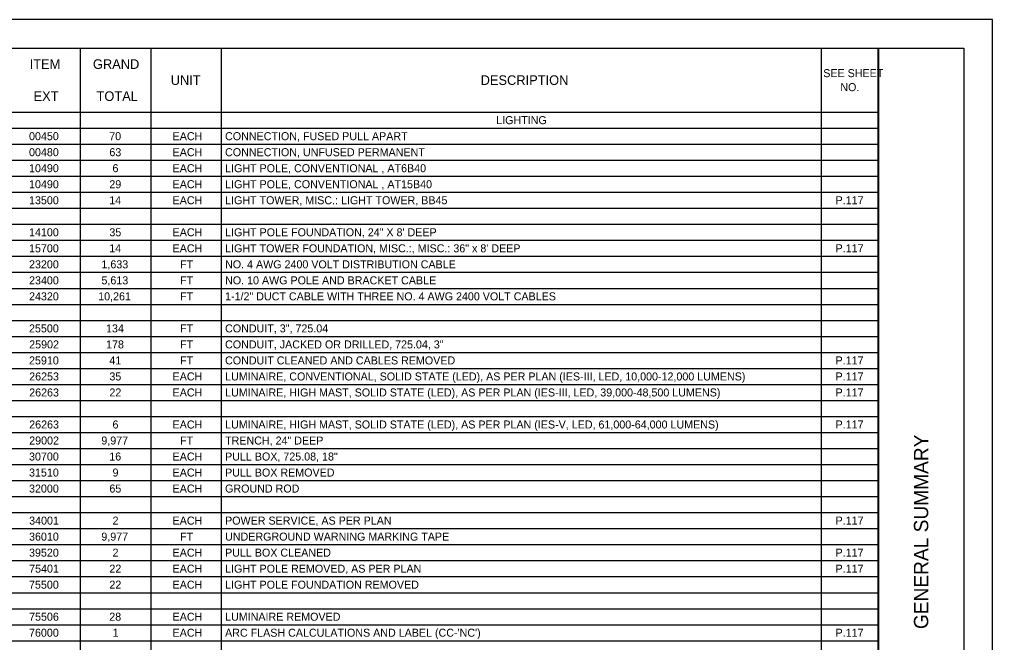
# Model space of a CAD drawing. Extents: x 0 to 34, y 0 to 22.
# Drawn here: x 16.98 to 34, y 11.11 to 22 of the extents above; entities that cross this region are included whole.
import ezdxf

# ---------------------------------------------------------------- set-up
doc = ezdxf.new("R2010")
doc.units = 0
for name, color, linetype in [('SH_Border', 7, 'Continuous'), ('SH_Cut_Line', 7, 'Continuous'), ('SH_Data', 7, 'Continuous'), ('SH_Text', 7, 'Continuous')]:
    doc.layers.add(name, color=color, linetype=linetype)

msp = doc.modelspace()

# ---------------------------------------------------------------- linework, layer by layer
at = {"layer": 'SH_Border'}
msp.add_line((32, 0.5), (32, 21.5), dxfattribs=at)
msp.add_lwpolyline([(1.5, 21.5), (33.5, 21.5), (33.5, 0.5), (1.5, 0.5)], close=True, dxfattribs=at)
at = {"layer": 'SH_Cut_Line'}
msp.add_lwpolyline([(0, 0), (34, 0), (34, 22), (0, 22)], close=True, dxfattribs=at)
at = {"layer": 'SH_Text'}
for p, q in [((1.5, 21.5), (32.004, 21.5)), ((18.036, 21.5), (18.036, 0.5)), ((19.272, 21.5), (19.272, 0.5)), ((20.507, 21.5), (20.507, 0.5)), ((30.999, 21.5), (30.999, 0.5)), ((32.004, 21.5), (32.004, 0.5)), ((1.5, 20.38), (32.004, 20.38)), ((1.5, 20.1), (32.004, 20.1)), ((1.5, 19.82), (32.004, 19.82)), ((1.5, 19.54), (32.004, 19.54)), ((1.5, 19.26), (32.004, 19.26)), ((1.5, 18.98), (32.004, 18.98)), ((1.5, 18.7), (32.004, 18.7)), ((1.5, 18.42), (32.004, 18.42)), ((1.5, 18.14), (32.004, 18.14)), ((1.5, 17.86), (32.004, 17.86)), ((1.5, 17.58), (32.004, 17.58)), ((1.5, 17.3), (32.004, 17.3)), ((1.5, 17.02), (32.004, 17.02)), ((1.5, 16.74), (32.004, 16.74)), ((1.5, 16.46), (32.004, 16.46)), ((1.5, 16.18), (32.004, 16.18)), ((1.5, 15.9), (32.004, 15.9)), ((1.5, 15.62), (32.004, 15.62)), ((1.5, 15.34), (32.004, 15.34)), ((1.5, 15.06), (32.004, 15.06)), ((1.5, 14.78), (32.004, 14.78)), ((1.5, 14.5), (32.004, 14.5)), ((1.5, 14.22), (32.004, 14.22)), ((1.5, 13.94), (32.004, 13.94)), ((1.5, 13.66), (32.004, 13.66)), ((1.5, 13.38), (32.004, 13.38)), ((1.5, 13.1), (32.004, 13.1)), ((1.5, 12.82), (32.004, 12.82)), ((1.5, 12.54), (32.004, 12.54)), ((1.5, 12.26), (32.004, 12.26)), ((1.5, 11.98), (32.004, 11.98)), ((1.5, 11.7), (32.004, 11.7)), ((1.5, 11.42), (32.004, 11.42)), ((1.5, 11.14), (32.004, 11.14))]:
    msp.add_line(p, q, dxfattribs=at)

# ---------------------------------------------------------------- texts
at = {"layer": 'SH_Data'}
msp.add_text('GENERAL SUMMARY', height=0.25, rotation=90, dxfattribs=at).set_placement((32.875, 11.344))
at = {"layer": 'SH_Text'}
for s, height, p in [('ITEM', 0.168, (17.154, 21.136)), ('GRAND', 0.168, (18.261, 21.136)), ('SEE SHEET ', 0.14, (31.038, 20.992)), ('UNIT', 0.168, (19.622, 20.856)), ('DESCRIPTION', 0.168, (25.044, 20.856)), ('NO.', 0.14, (31.337, 20.747)), ('EXT', 0.168, (17.222, 20.576)), ('TOTAL', 0.168, (18.324, 20.576)), ('LIGHTING', 0.14, (25.317, 20.17)), ('00450', 0.14, (17.143, 19.89)), ('70', 0.14, (18.546, 19.89)), ('EACH', 0.14, (19.655, 19.89)), ('CONNECTION, FUSED PULL APART', 0.14, (20.573, 19.89)), ('00480', 0.14, (17.143, 19.61)), ('63', 0.14, (18.549, 19.61)), ('EACH', 0.14, (19.655, 19.61)), ('CONNECTION, UNFUSED PERMANENT', 0.14, (20.573, 19.61)), ('10490', 0.14, (17.143, 19.33)), ('6', 0.14, (18.603, 19.33)), ('EACH', 0.14, (19.655, 19.33)), ('LIGHT POLE, CONVENTIONAL , AT6B40', 0.14, (20.573, 19.33)), ('10490', 0.14, (17.143, 19.05)), ('29', 0.14, (18.548, 19.05)), ('EACH', 0.14, (19.655, 19.05)), ('LIGHT POLE, CONVENTIONAL , AT15B40', 0.14, (20.573, 19.05)), ('13500', 0.14, (17.143, 18.77)), ('14', 0.14, (18.546, 18.77)), ('EACH', 0.14, (19.655, 18.77)), ('LIGHT TOWER, MISC.: LIGHT TOWER, BB45', 0.14, (20.573, 18.77)), ('P.117', 0.14, (31.254, 18.77)), ('14100', 0.14, (17.143, 18.21)), ('35', 0.14, (18.549, 18.21)), ('EACH', 0.14, (19.655, 18.21)), ('LIGHT POLE FOUNDATION, 24" X 8\' DEEP', 0.14, (20.573, 18.21)), ('15700', 0.14, (17.143, 17.93)), ('14', 0.14, (18.546, 17.93)), ('EACH', 0.14, (19.655, 17.93)), ('LIGHT TOWER FOUNDATION, MISC.:, MISC.: 36" x 8\' DEEP', 0.14, (20.573, 17.93)), ('P.117', 0.14, (31.254, 17.93)), ('23200', 0.14, (17.143, 17.65)), ('1,633', 0.14, (18.41, 17.65)), ('FT', 0.14, (19.786, 17.65)), ('NO. 4 AWG 2400 VOLT DISTRIBUTION CABLE', 0.14, (20.573, 17.65)), ('23400', 0.14, (17.143, 17.37)), ('5,613', 0.14, (18.41, 17.37)), ('FT', 0.14, (19.786, 17.37)), ('NO. 10 AWG POLE AND BRACKET CABLE', 0.14, (20.573, 17.37)), ('24320', 0.14, (17.143, 17.09)), ('10,261', 0.14, (18.353, 17.09)), ('FT', 0.14, (19.786, 17.09)), ('1-1/2" DUCT CABLE WITH THREE NO. 4 AWG 2400 VOLT CABLES', 0.14, (20.573, 17.09)), ('25500', 0.14, (17.143, 16.53)), ('134', 0.14, (18.49, 16.53)), ('FT', 0.14, (19.786, 16.53)), ('CONDUIT, 3", 725.04', 0.14, (20.573, 16.53)), ('25902', 0.14, (17.146, 16.25)), ('178', 0.14, (18.491, 16.25)), ('FT', 0.14, (19.786, 16.25)), ('CONDUIT, JACKED OR DRILLED, 725.04, 3"', 0.14, (20.573, 16.25)), ('25910', 0.14, (17.143, 15.97)), ('41', 0.14, (18.548, 15.97)), ('FT', 0.14, (19.786, 15.97)), ('CONDUIT CLEANED AND CABLES REMOVED', 0.14, (20.573, 15.97)), ('P.117', 0.14, (31.254, 15.97)), ('LUMINAIRE, CONVENTIONAL, SOLID STATE (LED), AS PER PLAN (IES-III, LED, 10,000-12,000 LUMENS)', 0.14, (20.573, 15.69)), ('26253', 0.14, (17.146, 15.69)), ('35', 0.14, (18.549, 15.69)), ('EACH', 0.14, (19.655, 15.69)), ('P.117', 0.14, (31.254, 15.69)), ('26263', 0.14, (17.146, 15.41)), ('22', 0.14, (18.549, 15.41)), ('EACH', 0.14, (19.655, 15.41)), ('LUMINAIRE, HIGH MAST, SOLID STATE (LED), AS PER PLAN (IES-III, LED, 39,000-48,500 LUMENS)', 0.14, (20.573, 15.41)), ('P.117', 0.14, (31.254, 15.41)), ('26263', 0.14, (17.146, 14.85)), ('6', 0.14, (18.603, 14.85)), ('EACH', 0.14, (19.655, 14.85)), ('LUMINAIRE, HIGH MAST, SOLID STATE (LED), AS PER PLAN (IES-V, LED, 61,000-64,000 LUMENS)', 0.14, (20.573, 14.85)), ('P.117', 0.14, (31.254, 14.85)), ('29002', 0.14, (17.146, 14.57)), ('9,977', 0.14, (18.408, 14.57)), ('FT', 0.14, (19.786, 14.57)), ('TRENCH, 24" DEEP', 0.14, (20.573, 14.57)), ('30700', 0.14, (17.143, 14.29)), ('16', 0.14, (18.547, 14.29)), ('EACH', 0.14, (19.655, 14.29)), ('PULL BOX, 725.08, 18"', 0.14, (20.573, 14.29)), ('31510', 0.14, (17.143, 14.01)), ('9', 0.14, (18.604, 14.01)), ('EACH', 0.14, (19.655, 14.01)), ('PULL BOX REMOVED', 0.14, (20.573, 14.01)), ('32000', 0.14, (17.143, 13.73)), ('65', 0.14, (18.549, 13.73)), ('EACH', 0.14, (19.655, 13.73)), ('GROUND ROD', 0.14, (20.573, 13.73)), ('34001', 0.14, (17.145, 13.17)), ('2', 0.14, (18.604, 13.17)), ('EACH', 0.14, (19.655, 13.17)), ('POWER SERVICE, AS PER PLAN', 0.14, (20.573, 13.17)), ('P.117', 0.14, (31.254, 13.17)), ('36010', 0.14, (17.143, 12.89)), ('9,977', 0.14, (18.408, 12.89)), ('FT', 0.14, (19.786, 12.89)), ('UNDERGROUND WARNING MARKING TAPE', 0.14, (20.573, 12.89)), ('39520', 0.14, (17.143, 12.61)), ('2', 0.14, (18.604, 12.61)), ('EACH', 0.14, (19.655, 12.61)), ('PULL BOX CLEANED', 0.14, (20.573, 12.61)), ('P.117', 0.14, (31.254, 12.61)), ('75401', 0.14, (17.145, 12.33)), ('22', 0.14, (18.549, 12.33)), ('EACH', 0.14, (19.655, 12.33)), ('LIGHT POLE REMOVED, AS PER PLAN', 0.14, (20.573, 12.33)), ('P.117', 0.14, (31.254, 12.33)), ('75500', 0.14, (17.143, 12.05)), ('22', 0.14, (18.549, 12.05)), ('EACH', 0.14, (19.655, 12.05)), ('LIGHT POLE FOUNDATION REMOVED', 0.14, (20.573, 12.05)), ('75506', 0.14, (17.144, 11.49)), ('28', 0.14, (18.547, 11.49)), ('EACH', 0.14, (19.655, 11.49)), ('LUMINAIRE REMOVED', 0.14, (20.573, 11.49)), ('76000', 0.14, (17.143, 11.21)), ('1', 0.14, (18.604, 11.21)), ('EACH', 0.14, (19.655, 11.21)), ("ARC FLASH CALCULATIONS AND LABEL (CC-'NC')", 0.14, (20.573, 11.21)), ('P.117', 0.14, (31.254, 11.21))]:
    msp.add_text(s, height=height, dxfattribs=at).set_placement(p)

doc.saveas('drawing.dxf')
